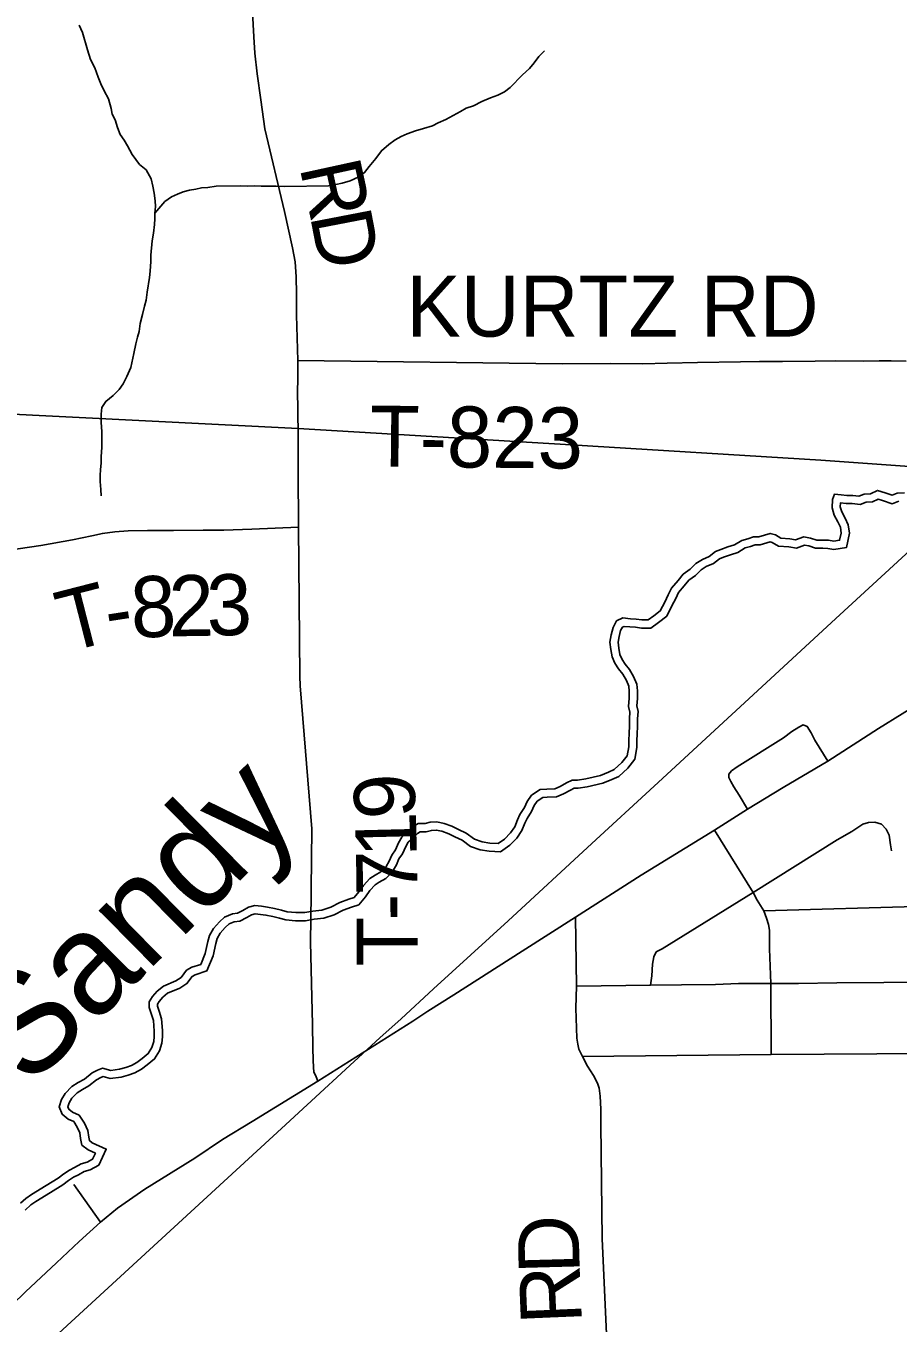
# Model space of a CAD drawing. Extents: x 0 to 34, y 0 to 22.
# Drawn here: x 6.308 to 7.12, y 17.784 to 18.992 of the extents above; entities that cross this region are included whole.
import ezdxf

# ---------------------------------------------------------------- set-up
doc = ezdxf.new("R2010")
doc.units = 0
doc.layers.add('Default', color=7, linetype='Continuous')

msp = doc.modelspace()

# ---------------------------------------------------------------- linework, layer by layer
at = {"layer": 'Default'}
for p, q in [((6.561, 18.6607), (6.5611, 18.6803)), ((6.5631, 18.3863), (6.5616, 18.5253)), ((6.9952, 18.1679), (7.1508, 18.1722)), ((6.3773, 17.8781), (6.3523, 17.913))]:
    msp.add_line(p, q, dxfattribs=at)
for points in [[(6.5611, 18.6803), (6.5598, 18.7226), (6.5598, 18.7425), (6.5594, 18.7584), (6.5587, 18.7721), (6.5561, 18.7854), (6.5487, 18.819), (6.5303, 18.8962), (6.5265, 18.9231), (6.5232, 18.9473), (6.5211, 18.9665), (6.5202, 18.9817), (6.5176, 19.0282)], [(6.378, 18.5543), (6.3776, 18.5601), (6.3771, 18.5677), (6.377, 18.5734), (6.3774, 18.5787), (6.378, 18.5848), (6.378, 18.5909), (6.3786, 18.5993), (6.3785, 18.6141), (6.378, 18.6225), (6.3779, 18.6305), (6.3786, 18.6366), (6.3823, 18.6423), (6.3891, 18.6478), (6.3948, 18.6532), (6.3985, 18.6585), (6.4018, 18.6654), (6.4056, 18.6739), (6.4084, 18.6869), (6.4102, 18.696), (6.4117, 18.7021), (6.4132, 18.7075), (6.4142, 18.7147), (6.4164, 18.7231), (6.4182, 18.7311), (6.4197, 18.7365), (6.4207, 18.7441), (6.4229, 18.7575), (6.4235, 18.7636), (6.4242, 18.7727), (6.4241, 18.7784), (6.4255, 18.7918), (6.4266, 18.799), (6.4276, 18.807), (6.4279, 18.8124), (6.4279, 18.8177), (6.4286, 18.8238), (6.4281, 18.8291), (6.4273, 18.8363), (6.4261, 18.8428), (6.4245, 18.8496), (6.4198, 18.8579), (6.4137, 18.8628), (6.4067, 18.8722), (6.4025, 18.8802), (6.3994, 18.8854), (6.3955, 18.8907), (6.3931, 18.8972), (6.3908, 18.9044), (6.3881, 18.9097), (6.3872, 18.915), (6.3848, 18.9241), (6.3806, 18.9316), (6.3775, 18.9381), (6.3751, 18.9441), (6.372, 18.9528), (6.3681, 18.9608), (6.3653, 18.9695), (6.3606, 18.9858), (6.3575, 18.9926)], [(6.4279, 18.8177), (6.4373, 18.8285), (6.4433, 18.8327), (6.449, 18.8351), (6.4543, 18.8375), (6.4603, 18.8391), (6.466, 18.8399), (6.4713, 18.8411), (6.4774, 18.8416), (6.485, 18.8428), (6.5074, 18.8431), (6.5143, 18.8428), (6.5211, 18.8429), (6.5268, 18.8426), (6.5409, 18.8428), (6.5489, 18.8425), (6.5896, 18.8431), (6.5964, 18.8443), (6.6025, 18.8456), (6.61, 18.8476), (6.6172, 18.8511), (6.6233, 18.8554), (6.6274, 18.8611), (6.6338, 18.8684), (6.639, 18.8757), (6.6458, 18.8815), (6.6518, 18.8858), (6.6575, 18.8889), (6.6628, 18.8913), (6.6707, 18.8941), (6.6783, 18.8964), (6.6867, 18.8988), (6.6919, 18.9016), (6.6991, 18.9047), (6.7127, 18.9121), (6.718, 18.9153), (6.7248, 18.9176), (6.7324, 18.9215), (6.7407, 18.9251), (6.7475, 18.9275), (6.7536, 18.9306), (6.7589, 18.9345), (6.7705, 18.9464), (6.7769, 18.9522), (6.7814, 18.9576), (6.7855, 18.9634), (6.7908, 18.9688)], [(6.5611, 18.6803), (6.8074, 18.6774), (6.8527, 18.6777), (6.8825, 18.6774), (6.905, 18.678), (6.9334, 18.6786), (6.9736, 18.679), (6.9912, 18.6793), (7.0127, 18.6794), (7.0431, 18.6797), (7.0618, 18.68), (7.0884, 18.6796), (7.1025, 18.68), (7.1139, 18.68), (7.1278, 18.6798)], [(6.5613, 18.5834), (6.5613, 18.6119), (6.5609, 18.6538), (6.561, 18.6607)], [(6.2768, 18.6314), (6.5613, 18.6169), (6.8158, 18.6017), (7.0484, 18.5875), (7.2089, 18.5761)], [(6.5616, 18.5253), (6.5613, 18.5775), (6.5613, 18.5834)], [(7.1263, 18.5572), (7.1195, 18.5568), (7.1146, 18.5549), (7.1081, 18.5571), (7.1012, 18.5594), (7.0944, 18.5563), (7.0887, 18.5559), (7.0838, 18.554), (7.0781, 18.5547), (7.0724, 18.5547), (7.0671, 18.5554), (7.061, 18.5558), (7.0591, 18.5508), (7.0588, 18.5432), (7.0607, 18.5364), (7.0642, 18.53), (7.0665, 18.525), (7.0673, 18.5197), (7.0658, 18.5129), (7.0605, 18.5121), (7.0555, 18.5129), (7.0502, 18.5132), (7.0445, 18.5132), (7.0388, 18.515), (7.0324, 18.5162), (7.0248, 18.5135), (7.0195, 18.5142), (7.0111, 18.5149), (7.0062, 18.5179), (7.0012, 18.5194), (6.9906, 18.5163), (6.9857, 18.5163), (6.9804, 18.5144), (6.9747, 18.5128), (6.9679, 18.5086), (6.9618, 18.5067), (6.955, 18.5044), (6.9501, 18.5025), (6.9444, 18.4979), (6.938, 18.4952), (6.9319, 18.4914), (6.9266, 18.486), (6.9202, 18.4814), (6.9153, 18.4754), (6.9092, 18.4685), (6.9062, 18.462), (6.9029, 18.4552), (6.8987, 18.4472), (6.8927, 18.4426), (6.8874, 18.4388), (6.8817, 18.4388), (6.8764, 18.4395), (6.871, 18.4398), (6.8638, 18.4406), (6.8581, 18.4379), (6.8548, 18.4318), (6.8529, 18.425), (6.8518, 18.4181), (6.8526, 18.4113), (6.8538, 18.4045), (6.8565, 18.3984), (6.8599, 18.3931), (6.8637, 18.3882), (6.8672, 18.3825), (6.8695, 18.3772), (6.8699, 18.3723), (6.8699, 18.3658), (6.8692, 18.3582), (6.8704, 18.3529), (6.87, 18.3469), (6.87, 18.3397), (6.8697, 18.3332), (6.8694, 18.3264), (6.8694, 18.3207), (6.8679, 18.3123), (6.863, 18.3059), (6.8558, 18.2994), (6.8505, 18.2971), (6.843, 18.294), (6.8293, 18.2909), (6.8217, 18.2897), (6.8168, 18.2897), (6.8115, 18.287), (6.8054, 18.2836), (6.8005, 18.2816), (6.7929, 18.2812), (6.7868, 18.2808), (6.7789, 18.2755), (6.7747, 18.2698), (6.7721, 18.264), (6.768, 18.2576), (6.7657, 18.2526), (6.7631, 18.2462), (6.7593, 18.2405), (6.7537, 18.2347), (6.7476, 18.2305), (6.74, 18.2309), (6.7328, 18.232), (6.7256, 18.2346), (6.718, 18.2403), (6.7107, 18.2436)], [(6.7074, 18.2368), (6.7141, 18.2337), (6.722, 18.2279), (6.7309, 18.2246), (6.7393, 18.2233), (6.7498, 18.2228), (6.7586, 18.2289), (6.7652, 18.2357), (6.7698, 18.2426), (6.7727, 18.2496), (6.7746, 18.2539), (6.7788, 18.2604), (6.7813, 18.2659), (6.7842, 18.2699), (6.7894, 18.2734), (6.7934, 18.2737), (6.8021, 18.2741), (6.8087, 18.2767), (6.8151, 18.2803), (6.8186, 18.2821), (6.8223, 18.2821), (6.8307, 18.2834), (6.8452, 18.2867), (6.8535, 18.2901), (6.86, 18.2929), (6.8686, 18.3007), (6.8751, 18.3092), (6.877, 18.32), (6.8769, 18.3262), (6.8773, 18.3328), (6.8776, 18.3395), (6.8776, 18.3467), (6.878, 18.3535), (6.8768, 18.3587), (6.8775, 18.3655), (6.8775, 18.3726), (6.8769, 18.3791), (6.8739, 18.386), (6.87, 18.3925), (6.8661, 18.3975), (6.8631, 18.402), (6.8611, 18.4067), (6.8601, 18.4124), (6.8594, 18.418), (6.8603, 18.4234), (6.8618, 18.4289), (6.8636, 18.4321), (6.8652, 18.4328), (6.8704, 18.4323), (6.8756, 18.432), (6.8812, 18.4312), (6.8898, 18.4312), (6.8972, 18.4365), (6.9047, 18.4422), (6.9096, 18.4518), (6.9131, 18.4588), (6.9156, 18.4643), (6.9211, 18.4705), (6.9254, 18.4759), (6.9315, 18.4802), (6.9367, 18.4854), (6.9415, 18.4885), (6.9483, 18.4913), (6.9539, 18.4958), (6.9576, 18.4973), (6.9642, 18.4995), (6.9711, 18.5017), (6.9777, 18.5058), (6.9827, 18.5072), (6.987, 18.5087), (6.9917, 18.5088), (7.0012, 18.5115), (7.0031, 18.5109), (7.0087, 18.5075), (7.0186, 18.5067), (7.0256, 18.5057), (7.033, 18.5083), (7.037, 18.5077), (7.0433, 18.5056), (7.05, 18.5056), (7.0547, 18.5053), (7.0605, 18.5045), (7.0721, 18.5062), (7.075, 18.5195), (7.0738, 18.5273), (7.071, 18.5334), (7.0678, 18.5393), (7.0664, 18.5441), (7.0666, 18.5478), (7.0719, 18.5471), (7.0776, 18.5471), (7.0848, 18.5462), (7.0904, 18.5484), (7.0963, 18.5488), (7.1017, 18.5513), (7.1057, 18.5499), (7.1147, 18.5468), (7.1211, 18.5493)], [(6.2707, 18.5006), (6.3216, 18.508), (6.3511, 18.5133), (6.3693, 18.5172), (6.3791, 18.5194), (6.3906, 18.5207), (6.4032, 18.5217), (6.421, 18.5219), (6.4453, 18.5222), (6.473, 18.5225), (6.4921, 18.5224), (6.5184, 18.5233), (6.5616, 18.5253)], [(6.2804, 17.7215), (6.5458, 17.9651), (6.6376, 18.0495), (6.6573, 18.0672), (6.6876, 18.0953), (6.757, 18.1586), (6.835, 18.2306), (6.8929, 18.284), (6.9655, 18.3508), (7.0659, 18.4436), (7.1351, 18.5072)], [(6.5736, 18.1876), (6.574, 18.2443), (6.5632, 18.3773), (6.5631, 18.3863)], [(6.7702, 18.1304), (6.8198, 18.1621), (6.881, 18.201), (6.9493, 18.2429), (6.9799, 18.2625), (7.0131, 18.2827), (7.0547, 18.3074), (7.102, 18.3377), (7.1461, 18.3649)], [(6.9625, 18.2919), (6.9625, 18.2952), (6.9652, 18.2984), (6.9702, 18.302), (7.0134, 18.329), (7.0213, 18.3349), (7.0277, 18.339), (7.0318, 18.341), (7.0356, 18.3396), (7.0392, 18.3337), (7.0428, 18.3267), (7.0547, 18.3074)], [(6.9799, 18.2625), (6.9722, 18.2755), (6.9674, 18.2835), (6.9645, 18.2883), (6.9625, 18.2919)], [(6.7107, 18.2436), (6.7046, 18.2466), (6.6974, 18.2493), (6.6906, 18.2507), (6.6845, 18.2503), (6.6796, 18.2492), (6.6731, 18.2491), (6.6678, 18.2461), (6.6629, 18.2411), (6.658, 18.2365), (6.655, 18.2312), (6.652, 18.2248), (6.6486, 18.2198), (6.6463, 18.2141), (6.6433, 18.2092), (6.6384, 18.2042), (6.6331, 18.2011), (6.6282, 18.1981), (6.6222, 18.1916), (6.618, 18.1855), (6.6135, 18.1802), (6.6086, 18.1786), (6.6002, 18.1755), (6.5919, 18.1713), (6.5836, 18.1686), (6.5752, 18.1675), (6.5676, 18.1663), (6.5593, 18.1662), (6.5513, 18.167), (6.546, 18.1684), (6.5395, 18.1699), (6.5327, 18.1714), (6.5274, 18.1722), (6.5209, 18.1729), (6.5152, 18.1713), (6.5099, 18.1683), (6.505, 18.1656), (6.5001, 18.1652), (6.4929, 18.1621), (6.488, 18.1575), (6.4827, 18.1514), (6.4789, 18.145), (6.4774, 18.1393), (6.4748, 18.1283), (6.4707, 18.118), (6.4624, 18.1153), (6.4574, 18.1126), (6.4525, 18.1058), (6.4476, 18.1027), (6.4359, 18.0977), (6.4302, 18.0931), (6.4257, 18.0882), (6.4227, 18.0832), (6.4227, 18.0779), (6.4246, 18.0722), (6.4266, 18.0658), (6.4274, 18.0559), (6.4274, 18.051), (6.427, 18.0461), (6.4252, 18.0407), (6.4218, 18.035), (6.4161, 18.0304), (6.4112, 18.0266), (6.4063, 18.0239), (6.401, 18.022), (6.3949, 18.0205), (6.3869, 18.0193), (6.3793, 18.0215), (6.3744, 18.0196), (6.3695, 18.0169), (6.3623, 18.0112), (6.3566, 18.0081), (6.3506, 18.0043), (6.3445, 17.9978), (6.3411, 17.9921), (6.3389, 17.9853), (6.3416, 17.9785), (6.3473, 17.9739), (6.3523, 17.9717), (6.3557, 17.9664), (6.358, 17.9611), (6.3588, 17.9558), (6.36, 17.9497), (6.3657, 17.9452), (6.3725, 17.9422), (6.3699, 17.9365), (6.365, 17.9338), (6.3593, 17.9323), (6.3532, 17.9288), (6.3483, 17.9265), (6.343, 17.9231), (6.3377, 17.9189), (6.3268, 17.912), (6.3131, 17.9036), (6.3078, 17.9001), (6.3029, 17.8956)], [(6.3071, 17.8891), (6.3125, 17.8941), (6.3172, 17.8972), (6.3308, 17.9056), (6.3421, 17.9127), (6.3474, 17.9169), (6.352, 17.9199), (6.3567, 17.9221), (6.3622, 17.9252), (6.3678, 17.9267), (6.3757, 17.931), (6.3826, 17.946), (6.3696, 17.9517), (6.3669, 17.9539), (6.3663, 17.9571), (6.3654, 17.9632), (6.3624, 17.97), (6.3574, 17.9777), (6.3513, 17.9805), (6.3479, 17.9831), (6.347, 17.9855), (6.3481, 17.989), (6.3506, 17.9933), (6.3554, 17.9984), (6.3604, 18.0016), (6.3665, 18.0049), (6.3737, 18.0106), (6.3776, 18.0127), (6.3797, 18.0135), (6.3864, 18.0116), (6.3964, 18.013), (6.4032, 18.0148), (6.4094, 18.017), (6.4154, 18.0203), (6.4208, 18.0245), (6.4276, 18.03), (6.4321, 18.0375), (6.4345, 18.0445), (6.435, 18.0507), (6.4349, 18.0563), (6.434, 18.0672), (6.4318, 18.0745), (6.4303, 18.0792), (6.4303, 18.0811), (6.4318, 18.0836), (6.4354, 18.0876), (6.4398, 18.0911), (6.4511, 18.096), (6.4578, 18.1001), (6.4626, 18.1068), (6.4654, 18.1083), (6.4764, 18.1119), (6.4821, 18.126), (6.4848, 18.1374), (6.486, 18.1421), (6.4889, 18.147), (6.4934, 18.1523), (6.4971, 18.1557), (6.5019, 18.1577), (6.5072, 18.1582), (6.5136, 18.1617), (6.5181, 18.1643), (6.5215, 18.1652), (6.5264, 18.1646), (6.5314, 18.164), (6.5379, 18.1625), (6.5441, 18.1611), (6.5499, 18.1595), (6.559, 18.1587), (6.5682, 18.1587), (6.5763, 18.16), (6.5853, 18.1612), (6.5948, 18.1643), (6.6033, 18.1686), (6.611, 18.1714), (6.6178, 18.1736), (6.6241, 18.1809), (6.6281, 18.1868), (6.6331, 18.1922), (6.637, 18.1946), (6.6431, 18.1981), (6.6493, 18.2045), (6.6531, 18.2107), (6.6553, 18.2162), (6.6586, 18.221), (6.6617, 18.2278), (6.664, 18.2318), (6.6682, 18.2357), (6.6725, 18.24), (6.6752, 18.2416), (6.6805, 18.2416), (6.6856, 18.2428), (6.69, 18.2431), (6.6953, 18.242), (6.7017, 18.2397), (6.7074, 18.2368)], [(6.8896, 18.0986), (6.8908, 18.1073), (6.8916, 18.1182), (6.8927, 18.1251), (6.8949, 18.1297), (6.9004, 18.1325), (6.9854, 18.1849), (7.0635, 18.2341), (7.0771, 18.2419), (7.0873, 18.2486), (7.0927, 18.2502), (7.0987, 18.2505), (7.1048, 18.2485), (7.1092, 18.244), (7.112, 18.2382), (7.1133, 18.2294), (7.1142, 18.2236)], [(7.0019, 18.0341), (7.0016, 18.1001), (7.0006, 18.1325), (7.0005, 18.142), (7.0005, 18.15), (6.9995, 18.155), (6.9978, 18.1609), (6.9952, 18.1679), (6.989, 18.1779), (6.9854, 18.1849), (6.9493, 18.2429)], [(6.5797, 18.0093), (6.5781, 18.0132), (6.5761, 18.018), (6.5757, 18.022), (6.5755, 18.029), (6.5752, 18.0399), (6.5749, 18.062), (6.573, 18.1386), (6.5735, 18.1827), (6.5736, 18.1876)], [(6.8492, 17.7603), (6.8446, 17.8623), (6.8432, 17.969), (6.8435, 17.9831), (6.8427, 17.9954), (6.8417, 18.0026), (6.8404, 18.0075), (6.8364, 18.0146), (6.831, 18.0233), (6.8262, 18.0322), (6.8229, 18.039), (6.8219, 18.0438), (6.8211, 18.0493), (6.8202, 18.0773), (6.8208, 18.0978), (6.8198, 18.1621)], [(6.282, 17.7887), (6.3073, 17.813), (6.3362, 17.8402), (6.3575, 17.8601), (6.3773, 17.8781), (6.3931, 17.8911), (6.4187, 17.9087), (6.4651, 17.9375), (6.491, 17.9548), (6.5185, 17.9718), (6.5797, 18.0093), (6.6681, 18.065), (6.6821, 18.0745), (6.7065, 18.0896), (6.7702, 18.1304)], [(6.8208, 18.0978), (6.8896, 18.0986), (6.9184, 18.099), (6.9503, 18.0993), (6.9717, 18.1003), (7.0016, 18.1001)], [(7.0016, 18.1001), (7.0276, 18.1003), (7.0631, 18.1008), (7.1509, 18.1013)], [(6.8262, 18.0322), (7.0019, 18.0341), (7.1499, 18.035)]]:
    msp.add_lwpolyline(points, dxfattribs=at)

# ---------------------------------------------------------------- texts
for s, height, rotation, p in [('R', 0.0568, 282.2706, (6.5625, 18.8608)), ('D', 0.0568, 280.9249, (6.5723, 18.8155)), ('KURTZ RD', 0.05682, 359.999, (6.6621, 18.7026)), ('T-823', 0.05682, 359.4386, (6.628, 18.5816)), ('8', 0.0568, 2.3684, (6.4065, 18.422)), ('2', 0.0568, 0.8795, (6.4411, 18.4234)), ('3', 0.0568, 1.4839, (6.4767, 18.424)), ('T', 0.0568, 14.4011, (6.3454, 18.4083)), ('-', 0.0568, 8.8091, (6.3851, 18.4186)), ('Sandy', 0.09471, 44.6232, (6.3102, 18.0015)), ('9', 0.0568, 92.8113, (6.6712, 18.2549)), ('1', 0.0568, 91.4304, (6.6721, 18.2184)), ('7', 0.0568, 90.5411, (6.6725, 18.1824)), ('-', 0.0568, 90.1314, (6.6726, 18.1587)), ('T', 0.0568, 90.0129, (6.6726, 18.116)), ('D', 0.0568, 91.5848, (6.8238, 17.8306)), ('R', 0.0568, 92.4323, (6.8258, 17.7842))]:
    msp.add_text(s, height=height, rotation=rotation, dxfattribs=at).set_placement(p)

doc.saveas('drawing.dxf')
